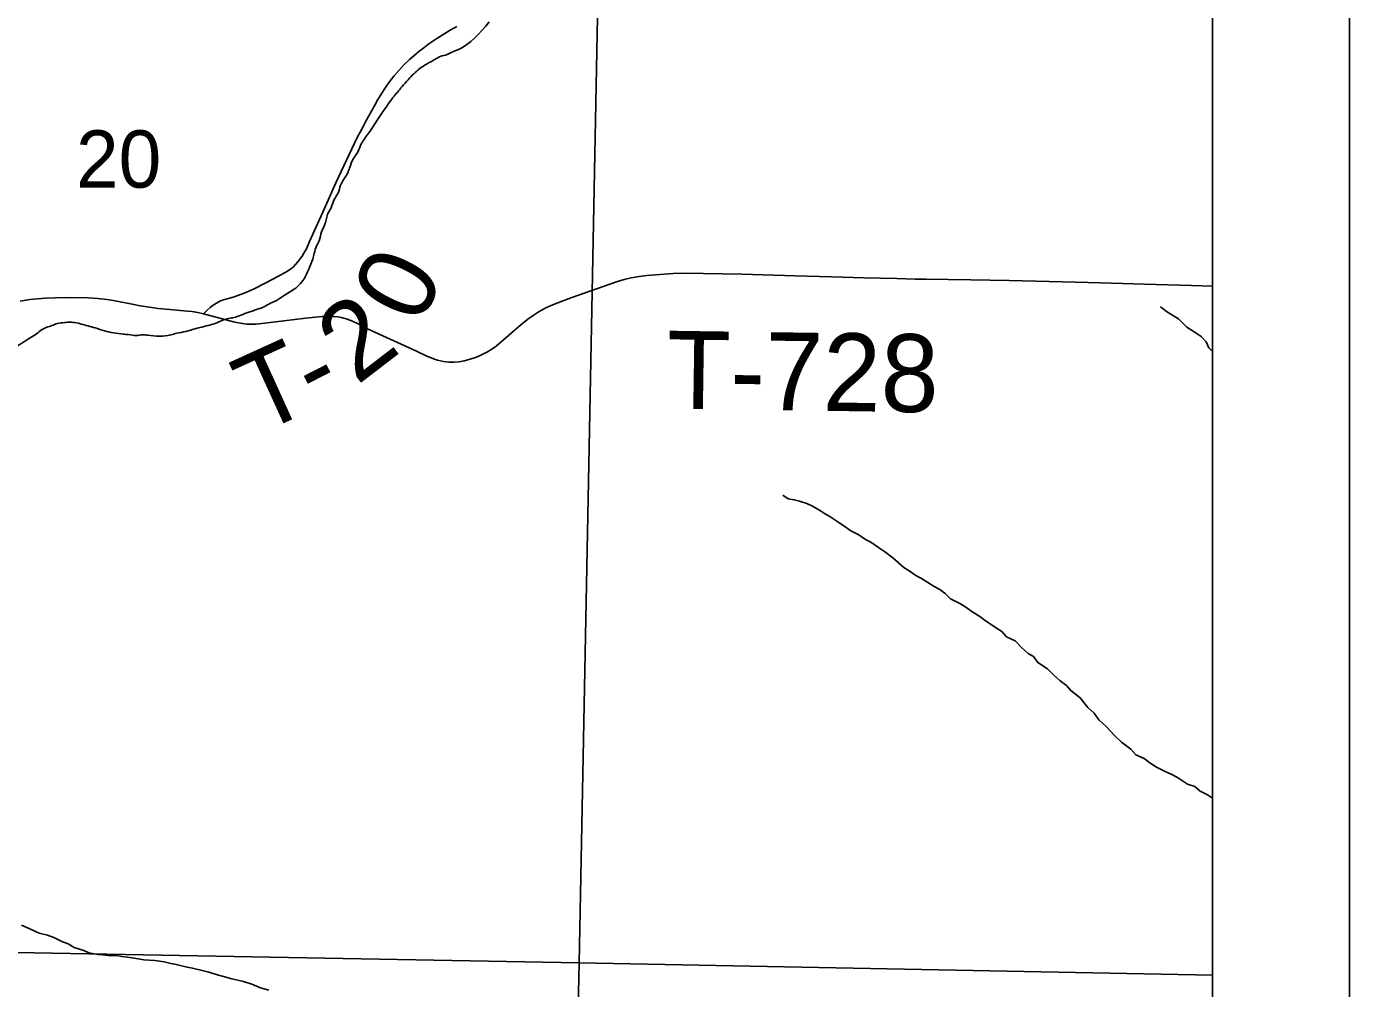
# Model space of a CAD drawing. Extents: x 0 to 34, y 0 to 22.
# Drawn here: x 29.451 to 30.417, y 15.474 to 16.176 of the extents above; entities that cross this region are included whole.
import ezdxf

# ---------------------------------------------------------------- set-up
doc = ezdxf.new("R2010")
doc.units = 0
for name, color, linetype in [('GM_X_Corporation', 7, 'Continuous'), ('GM_X_Minor_River', 7, 'Continuous'), ('GM_X_Section_Text', 7, 'Continuous'), ('GM_X_Township_Road', 7, 'Continuous'), ('GM_X_Township_Road_Text', 7, 'Continuous'), ('SH_Data', 7, 'Continuous')]:
    doc.layers.add(name, color=color, linetype=linetype)

msp = doc.modelspace()

# ---------------------------------------------------------------- linework, layer by layer
at = {"layer": 'GM_X_Corporation'}
for points in [[(27.80309, 14.50906), (28.4032, 14.497), (28.78527, 14.48932), (29.17126, 14.4832), (29.23672, 14.48221), (30.30982, 14.46403), (30.31667, 14.46388), (30.31667, 20.9), (27.1022, 20.9)], [(27.80309, 14.50906), (28.4032, 14.497), (28.78527, 14.48932), (29.17126, 14.4832), (29.23672, 14.48221), (30.30982, 14.46403), (30.31667, 14.46388), (30.31667, 20.36493), (29.55027, 20.37882), (27.67509, 20.4106)]]:
    msp.add_lwpolyline(points, dxfattribs=at)
for points in [[(29.87406, 16.50997), (29.85435, 15.49328), (28.84638, 15.51159), (28.863, 16.5324)], [(30.31667, 15.48431), (30.31667, 16.49907), (29.87406, 16.50997), (29.85435, 15.49328)], [(28.84638, 15.51159), (29.85435, 15.49328), (29.83158, 14.4749), (28.83541, 14.49263)], [(30.31667, 14.46631), (30.31667, 15.48431), (29.85435, 15.49328), (29.83158, 14.4749)]]:
    msp.add_lwpolyline(points, close=True, dxfattribs=at)
at = {"layer": 'GM_X_Minor_River'}
for points in [[(30.27873, 15.972), (30.28372, 15.96791), (30.29175, 15.96313), (30.29791, 15.95718), (30.3025, 15.95422), (30.30825, 15.95016), (30.3121, 15.94643), (30.31406, 15.94192), (30.31667, 15.93919)], [(30.003, 15.8344), (30.00683, 15.83182), (30.01138, 15.83114), (30.01518, 15.83007), (30.02051, 15.82827), (30.0247, 15.82645), (30.02929, 15.82388), (30.03388, 15.82093), (30.03809, 15.81835), (30.04307, 15.81503), (30.04843, 15.81133), (30.05264, 15.80837), (30.05837, 15.80544), (30.06335, 15.80212), (30.06716, 15.80029), (30.07291, 15.79623), (30.07712, 15.79327), (30.08325, 15.78883), (30.09132, 15.78178), (30.09591, 15.77882), (30.10012, 15.77587), (30.10432, 15.77367), (30.11351, 15.76777), (30.11771, 15.76557), (30.12154, 15.7626), (30.12539, 15.75888), (30.13265, 15.75522), (30.13648, 15.75264), (30.1403, 15.75005), (30.14681, 15.746), (30.15064, 15.74303), (30.1583, 15.73786), (30.16289, 15.73491), (30.16636, 15.73118), (30.17247, 15.72826), (30.17709, 15.72342), (30.18209, 15.71896), (30.18591, 15.71675), (30.18902, 15.71225), (30.19628, 15.70784), (30.20052, 15.70336), (30.20552, 15.6989), (30.21011, 15.69557), (30.21321, 15.69184), (30.22011, 15.68666), (30.22553, 15.67955), (30.23014, 15.67546), (30.23363, 15.6706), (30.23901, 15.66577), (30.24557, 15.65868), (30.25019, 15.65421), (30.25709, 15.64903), (30.26056, 15.64492), (30.26666, 15.64238), (30.27088, 15.63904), (30.27585, 15.6361), (30.28196, 15.63279), (30.28654, 15.63098), (30.29112, 15.62841), (30.29839, 15.62361), (30.30372, 15.62181), (30.30756, 15.61847), (30.31291, 15.61591), (30.31667, 15.61327)], [(29.62785, 15.47321), (29.62176, 15.475), (29.61529, 15.47753), (29.6092, 15.4797), (29.60084, 15.48144), (29.59475, 15.48323), (29.59095, 15.48429), (29.5841, 15.48645), (29.57917, 15.48749), (29.57195, 15.48926), (29.56815, 15.48995), (29.56017, 15.49208), (29.55637, 15.49277), (29.55143, 15.49382), (29.54461, 15.49483), (29.53665, 15.49544), (29.53248, 15.49613), (29.52792, 15.4968), (29.52072, 15.49781), (29.51654, 15.49849), (29.51238, 15.49842), (29.5067, 15.49907), (29.50291, 15.49939), (29.49646, 15.50041), (29.49264, 15.50223), (29.48579, 15.50438), (29.48121, 15.50695), (29.47663, 15.50877), (29.47091, 15.5117), (29.46634, 15.51351), (29.46026, 15.51492), (29.45111, 15.51892), (29.44729, 15.52075)]]:
    msp.add_lwpolyline(points, dxfattribs=at)
for points in [[(29.68669, 16.07321), (29.6896, 16.08009), (29.69218, 16.08392), (29.69473, 16.08966), (29.69988, 16.09771), (29.70395, 16.10347), (29.70726, 16.10883), (29.71132, 16.11459), (29.71501, 16.11997), (29.71834, 16.12458), (29.72168, 16.12843), (29.72501, 16.13266), (29.72946, 16.13767), (29.73355, 16.14191), (29.73803, 16.14578), (29.74326, 16.14929), (29.74963, 16.15281), (29.75338, 16.15478), (29.7579, 16.156), (29.76203, 16.15796), (29.76579, 16.15955), (29.78864, 16.17987)], [(29.20809, 15.82995), (29.21292, 15.83496), (29.21775, 15.84036), (29.22373, 15.84463), (29.22783, 15.84812), (29.23267, 15.85275), (29.2364, 15.85585), (29.24085, 15.86124), (29.24678, 15.86817), (29.25276, 15.87245), (29.25876, 15.87559), (29.26589, 15.87875), (29.27266, 15.88114), (29.27643, 15.88197), (29.28285, 15.88284), (29.28965, 15.88334), (29.30743, 15.88366), (29.31611, 15.88496), (29.31988, 15.8854), (29.32555, 15.88588), (29.33121, 15.88675), (29.33536, 15.88758), (29.33988, 15.8888), (29.34404, 15.88925), (29.34969, 15.89049), (29.35572, 15.89173), (29.36138, 15.89297), (29.36552, 15.89419), (29.37003, 15.89578), (29.37418, 15.89662), (29.37983, 15.89786), (29.38435, 15.89945), (29.38885, 15.90181), (29.39448, 15.90418), (29.39935, 15.90693), (29.40572, 15.91083), (29.41095, 15.91471), (29.41506, 15.91744), (29.42547, 15.92824), (29.42995, 15.93174), (29.43479, 15.93637), (29.44039, 15.94064), (29.44675, 15.94493), (29.45236, 15.94844), (29.45723, 15.95156), (29.46471, 15.95662), (29.46847, 15.95783), (29.47223, 15.95941), (29.47751, 15.96027), (29.48166, 15.96072), (29.48621, 15.96042), (29.49077, 15.95937), (29.49571, 15.95794), (29.50103, 15.95652), (29.50788, 15.95437), (29.51434, 15.95297), (29.52154, 15.95196), (29.52533, 15.95165), (29.53102, 15.951), (29.53556, 15.95146), (29.53934, 15.95114), (29.55637, 15.95145), (29.56051, 15.95266), (29.56729, 15.95392), (29.57369, 15.95593), (29.57746, 15.95676), (29.58349, 15.95839), (29.59026, 15.9604), (29.59477, 15.96238), (29.59967, 15.96361), (29.60344, 15.96443), (29.6087, 15.96642), (29.61472, 15.96843), (29.61885, 15.97002), (29.62375, 15.97162), (29.62787, 15.97397), (29.63237, 15.97595), (29.63612, 15.97829), (29.64023, 15.98102), (29.64398, 15.98336), (29.64846, 15.98647), (29.65292, 15.99148), (29.65512, 15.99531), (29.65694, 15.99951), (29.65984, 16.00677), (29.6609, 16.01096), (29.6627, 16.0163), (29.66453, 16.02012), (29.66631, 16.0266), (29.66849, 16.03156), (29.67063, 16.03918), (29.67319, 16.04416), (29.67573, 16.05065), (29.6783, 16.05486), (29.6801, 16.06058), (29.68524, 16.06939), (29.68669, 16.07321)]]:
    msp.add_spline(points, degree=3, dxfattribs=at)
at = {"layer": 'GM_X_Township_Road'}
for points in [[(29.58018, 15.9669), (29.58282, 15.96944), (29.58487, 15.97139), (29.58709, 15.97314), (29.58948, 15.97466), (29.59199, 15.97596), (29.59463, 15.977), (29.59734, 15.97779), (29.60174, 15.97904), (29.6051, 15.98008), (29.60985, 15.98197), (29.61649, 15.9849), (29.62548, 15.98948), (29.63438, 15.99415), (29.64141, 15.99801), (29.64373, 15.99956), (29.64555, 16.00095), (29.6473, 16.00281), (29.64896, 16.00474), (29.65053, 16.00675), (29.652, 16.00884), (29.65337, 16.01099), (29.65523, 16.01433), (29.65753, 16.0195), (29.66709, 16.0409), (29.67666, 16.0623), (29.69238, 16.09549), (29.69445, 16.09948), (29.69656, 16.10344), (29.69869, 16.1074), (29.70084, 16.11134), (29.70302, 16.11527), (29.70523, 16.11918), (29.70746, 16.12308), (29.70946, 16.12653), (29.71141, 16.12968), (29.71346, 16.13278), (29.7156, 16.1358), (29.71901, 16.1402), (29.72262, 16.14443), (29.72644, 16.14849), (29.73045, 16.15234), (29.73366, 16.15517), (29.73724, 16.15812), (29.74089, 16.16099), (29.74462, 16.16375), (29.75034, 16.16772), (29.75425, 16.17024), (29.76022, 16.17382), (29.76492, 16.17643)], [(29.44627, 15.97603), (29.45342, 15.97718), (29.45877, 15.97775), (29.46469, 15.97817), (29.47175, 15.97858), (29.47923, 15.97882), (29.49584, 15.9785), (29.50291, 15.97792), (29.50973, 15.97718), (29.51573, 15.97627), (29.52806, 15.97373), (29.5339, 15.97274), (29.54056, 15.97167), (29.5471, 15.9708), (29.55544, 15.96995), (29.56308, 15.96929), (29.56834, 15.96879), (29.57187, 15.96838), (29.57607, 15.96772), (29.58018, 15.9669), (29.60188, 15.96099), (29.6055, 15.96025), (29.60878, 15.95967), (29.61158, 15.95934), (29.61462, 15.95926), (29.6184, 15.95934), (29.62268, 15.95967), (29.65482, 15.96353), (29.6618, 15.96444), (29.66682, 15.96476), (29.67068, 15.96493), (29.67471, 15.96485), (29.67825, 15.96452), (29.68178, 15.96386), (29.6849, 15.96288), (29.68877, 15.9614), (29.69345, 15.95918), (29.69986, 15.95597), (29.73546, 15.93953), (29.74253, 15.93624), (29.74787, 15.93386), (29.75092, 15.93287), (29.75535, 15.93205), (29.7593, 15.93156), (29.76299, 15.93147), (29.76661, 15.9318), (29.7704, 15.93246), (29.77483, 15.93361), (29.77854, 15.93493), (29.78215, 15.93649), (29.78733, 15.93912), (29.79045, 15.94093), (29.79382, 15.94331), (29.81174, 15.95868), (29.81684, 15.9628), (29.82078, 15.9655), (29.82514, 15.96847), (29.83048, 15.97143), (29.83673, 15.97414), (29.84906, 15.97866), (29.88161, 15.99017), (29.88729, 15.99189), (29.8923, 15.99304), (29.89806, 15.99403), (29.90364, 15.99469), (29.9131, 15.99551), (29.92296, 15.99617), (29.93102, 15.99641), (29.9731, 15.9957), (30.01204, 15.99458), (30.03862, 15.99382), (30.06238, 15.99315), (30.08621, 15.99247), (30.09962, 15.99214), (30.10726, 15.99206), (30.14014, 15.99153), (30.16821, 15.99107), (30.20705, 15.99016), (30.23497, 15.98951), (30.26698, 15.98848), (30.30141, 15.98738), (30.31667, 15.98709)]]:
    msp.add_lwpolyline(points, dxfattribs=at)
at = {"layer": 'SH_Data'}
for points in [[(23.41667, 21), (30.41667, 21), (30.41667, 14), (23.41667, 14)], [(23.51667, 20.9), (30.31667, 20.9), (30.31667, 14.1), (23.51667, 14.1)]]:
    msp.add_lwpolyline(points, close=True, dxfattribs=at)

# ---------------------------------------------------------------- texts
at = {"layer": 'GM_X_Section_Text'}
msp.add_text('20', height=0.041856, rotation=0.00001, dxfattribs=at).set_placement((29.48702, 16.05884))
at = {"layer": 'GM_X_Township_Road_Text'}
for s, height, rotation, p in [('0', 0.05682, 63.5797, (29.73756, 15.95708)), ('2', 0.05682, 37.52126, (29.69205, 15.91419)), ('T', 0.05682, 24.4851, (29.62053, 15.87872)), ('T-728', 0.056818, 359.17845, (29.91794, 15.89768)), ('-', 0.05682, 27.05129, (29.66171, 15.89754))]:
    msp.add_text(s, height=height, rotation=rotation, dxfattribs=at).set_placement(p)

doc.saveas('drawing.dxf')
